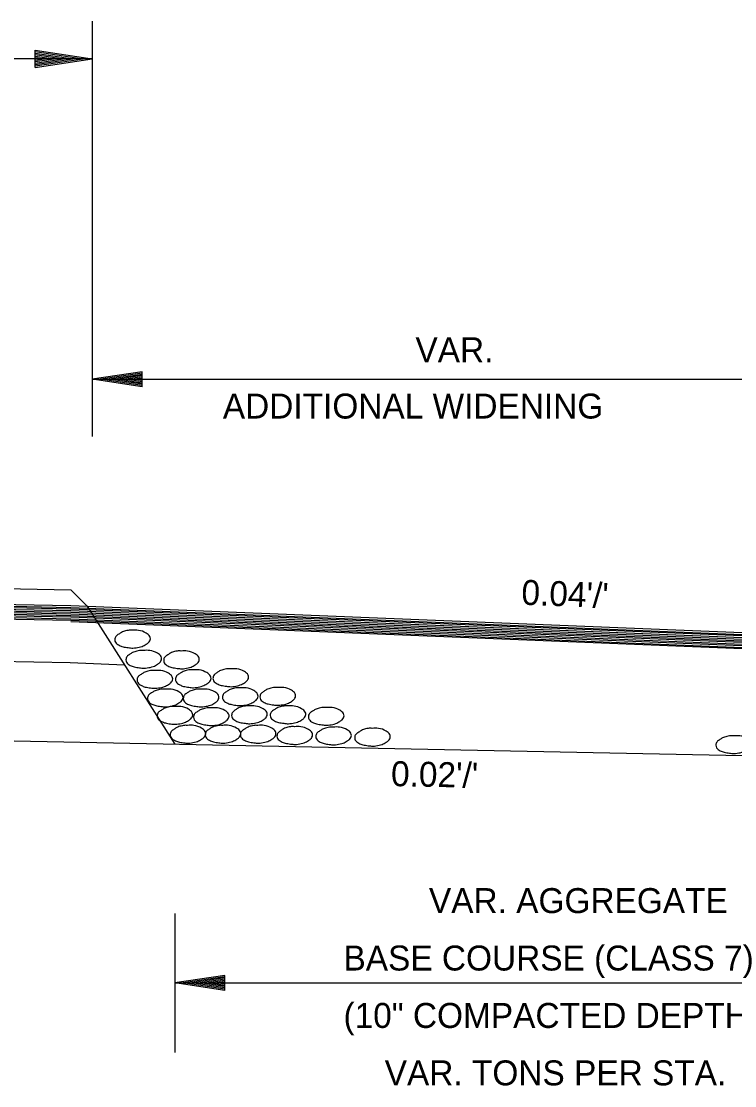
# Model space of a CAD drawing. Extents: x 1035 to 3550, y 35 to 1510.
# Drawn here: x 2318.4 to 2489.7, y 571 to 826.6 of the extents above; entities that cross this region are included whole.
import ezdxf

# ---------------------------------------------------------------- set-up
doc = ezdxf.new("R2010")
doc.units = 0
doc.layers.add('Default', color=7, linetype='Continuous')

msp = doc.modelspace()

# ---------------------------------------------------------------- linework, layer by layer
at = {"layer": 'Default'}
for p, q in [((2335.41, 826.63), (2335.41, 726.95)), ((2321.71, 819.67), (2335.41, 817.63)), ((2321.71, 815.57), (2321.71, 819.67)), ((2321.71, 819.34), (2333.14, 817.63)), ((2321.71, 818.98), (2330.77, 817.63)), ((2321.71, 818.65), (2328.48, 817.63)), ((2321.71, 818.28), (2326.17, 817.63)), ((2335.41, 817.63), (2055.5, 817.63)), ((2321.71, 817.95), (2323.89, 817.63)), ((2321.71, 815.57), (2335.41, 817.63)), ((2321.71, 816.94), (2326.17, 817.63)), ((2321.71, 816.25), (2330.77, 817.63)), ((2321.71, 815.91), (2333.14, 817.63)), ((2321.71, 816.61), (2328.48, 817.63)), ((2321.71, 817.3), (2323.89, 817.63)), ((2347.41, 742.45), (2335.41, 740.65)), ((2347.41, 742.15), (2337.41, 740.65)), ((2347.41, 741.84), (2339.48, 740.65)), ((2347.41, 741.54), (2341.48, 740.65)), ((2347.41, 738.85), (2347.41, 742.45)), ((2335.41, 740.65), (2512.84, 740.65)), ((2347.41, 738.85), (2335.41, 740.65)), ((2347.41, 739.15), (2337.41, 740.65)), ((2347.41, 739.46), (2339.48, 740.65)), ((2347.41, 739.76), (2341.48, 740.65)), ((2347.41, 741.24), (2343.51, 740.65)), ((2347.41, 740.07), (2343.51, 740.65)), ((2347.41, 740.93), (2345.51, 740.65)), ((2347.41, 740.37), (2345.51, 740.65)), ((2261.72, 687.66), (2330.33, 686.31)), ((2261.72, 687.24), (2330.33, 685.87)), ((2261.72, 686.92), (2330.33, 685.54)), ((2261.72, 686.51), (2330.33, 685.12)), ((2261.72, 686.11), (2330.33, 684.7)), ((2261.72, 685.73), (2330.33, 684.34)), ((2261.72, 685.34), (2330.33, 683.96)), ((2330.33, 686.31), (2557.51, 677.18)), ((2330.33, 685.87), (2557.79, 676.73)), ((2330.33, 685.54), (2557.97, 676.45)), ((2330.33, 685.12), (2558.27, 675.98)), ((2334.24, 686.17), (2355.28, 653.05)), ((2261.72, 684.95), (2330.33, 683.58)), ((2261.72, 684.52), (2330.33, 683.16)), ((2261.72, 684.14), (2330.33, 682.79)), ((2330.33, 684.7), (2558.52, 675.59)), ((2330.33, 684.34), (2558.81, 675.13)), ((2330.33, 683.96), (2559.01, 674.8)), ((2330.33, 683.58), (2559.3, 674.35)), ((2330.33, 683.16), (2559.55, 673.96)), ((2330.33, 682.79), (2559.84, 673.5)), ((2330.33, 682.46), (2560.01, 673.24)), ((2261.52, 673.98), (2330.13, 672.63)), ((2330.13, 672.63), (2343.16, 672.12)), ((2261.14, 654.92), (2647.44, 647.2)), ((2355.29, 612.37), (2355.29, 579.01)), ((2367.29, 597.49), (2355.29, 595.69)), ((2355.29, 595.69), (2557.51, 595.69)), ((2367.29, 593.89), (2355.29, 595.69)), ((2367.29, 597.19), (2357.29, 595.69)), ((2367.29, 594.19), (2357.29, 595.69)), ((2367.29, 596.88), (2359.36, 595.69)), ((2367.29, 594.5), (2359.36, 595.69)), ((2367.29, 596.58), (2361.36, 595.69)), ((2367.29, 594.8), (2361.36, 595.69)), ((2367.29, 596.28), (2363.39, 595.69)), ((2367.29, 595.11), (2363.39, 595.69)), ((2367.29, 595.97), (2365.39, 595.69)), ((2367.29, 595.41), (2365.39, 595.69)), ((2367.29, 593.89), (2367.29, 597.49))]:
    msp.add_line(p, q, dxfattribs=at)
msp.add_lwpolyline([(2261.72, 691.48), (2330.33, 690.11), (2334.24, 686.17)], dxfattribs=at)
for points in [[(2345.03, 680.37), (2346.56, 680.36), (2348.38, 679.72), (2349.27, 678.89), (2349.39, 678.35), (2348.93, 677.43), (2348.41, 677.04), (2347.41, 676.52), (2345.95, 676.18), (2345.19, 676.1), (2344.08, 676.21), (2342.82, 676.42), (2341.87, 676.79), (2340.99, 677.52), (2340.84, 678.1), (2341.1, 678.92), (2341.8, 679.45), (2342.44, 679.87), (2343.46, 680.22), (2344.09, 680.36), (2345.03, 680.37)], [(2347.72, 675.54), (2349.25, 675.53), (2351.07, 674.89), (2351.96, 674.06), (2352.08, 673.52), (2351.62, 672.6), (2351.1, 672.21), (2350.1, 671.69), (2348.64, 671.35), (2347.88, 671.27), (2346.77, 671.38), (2345.51, 671.59), (2344.56, 671.96), (2343.68, 672.69), (2343.53, 673.27), (2343.79, 674.09), (2344.49, 674.62), (2345.13, 675.04), (2346.15, 675.39), (2346.78, 675.53), (2347.72, 675.54)], [(2356.78, 675.4), (2358.31, 675.39), (2360.13, 674.75), (2361.02, 673.92), (2361.14, 673.38), (2360.68, 672.46), (2360.16, 672.07), (2359.16, 671.55), (2357.7, 671.21), (2356.94, 671.13), (2355.83, 671.24), (2354.57, 671.45), (2353.62, 671.82), (2352.74, 672.55), (2352.59, 673.13), (2352.85, 673.95), (2353.55, 674.48), (2354.19, 674.9), (2355.21, 675.25), (2355.84, 675.39), (2356.78, 675.4)], [(2350.39, 670.71), (2351.92, 670.7), (2353.74, 670.06), (2354.63, 669.23), (2354.75, 668.69), (2354.29, 667.77), (2353.77, 667.38), (2352.77, 666.86), (2351.31, 666.52), (2350.55, 666.44), (2349.44, 666.55), (2348.18, 666.76), (2347.23, 667.13), (2346.35, 667.86), (2346.2, 668.44), (2346.46, 669.26), (2347.16, 669.79), (2347.8, 670.21), (2348.82, 670.56), (2349.45, 670.7), (2350.39, 670.71)], [(2359.6, 670.86), (2361.13, 670.85), (2362.95, 670.21), (2363.84, 669.38), (2363.96, 668.84), (2363.5, 667.92), (2362.98, 667.53), (2361.98, 667.01), (2360.52, 666.67), (2359.76, 666.59), (2358.65, 666.7), (2357.39, 666.91), (2356.44, 667.28), (2355.56, 668.01), (2355.41, 668.59), (2355.67, 669.41), (2356.37, 669.94), (2357.01, 670.36), (2358.03, 670.71), (2358.66, 670.85), (2359.6, 670.86)], [(2368.62, 671.11), (2370.15, 671.1), (2371.97, 670.46), (2372.86, 669.63), (2372.98, 669.09), (2372.52, 668.17), (2372, 667.78), (2371, 667.26), (2369.54, 666.92), (2368.78, 666.84), (2367.67, 666.95), (2366.41, 667.16), (2365.46, 667.53), (2364.58, 668.26), (2364.43, 668.84), (2364.69, 669.66), (2365.39, 670.19), (2366.03, 670.61), (2367.05, 670.96), (2367.68, 671.1), (2368.62, 671.11)], [(2352.88, 666.25), (2354.41, 666.24), (2356.23, 665.6), (2357.12, 664.77), (2357.24, 664.23), (2356.78, 663.31), (2356.26, 662.92), (2355.26, 662.4), (2353.8, 662.06), (2353.04, 661.98), (2351.93, 662.09), (2350.67, 662.3), (2349.72, 662.67), (2348.84, 663.4), (2348.69, 663.98), (2348.95, 664.8), (2349.65, 665.33), (2350.29, 665.75), (2351.31, 666.1), (2351.94, 666.24), (2352.88, 666.25)], [(2361.49, 666.25), (2363.02, 666.24), (2364.84, 665.6), (2365.73, 664.77), (2365.85, 664.23), (2365.39, 663.31), (2364.87, 662.92), (2363.87, 662.4), (2362.41, 662.06), (2361.65, 661.98), (2360.54, 662.09), (2359.28, 662.3), (2358.33, 662.67), (2357.45, 663.4), (2357.3, 663.98), (2357.56, 664.8), (2358.26, 665.33), (2358.9, 665.75), (2359.92, 666.1), (2360.55, 666.24), (2361.49, 666.25)], [(2370.89, 666.55), (2372.42, 666.54), (2374.24, 665.9), (2375.13, 665.07), (2375.25, 664.53), (2374.79, 663.61), (2374.27, 663.22), (2373.27, 662.7), (2371.81, 662.36), (2371.05, 662.28), (2369.94, 662.39), (2368.68, 662.6), (2367.73, 662.97), (2366.85, 663.7), (2366.7, 664.28), (2366.96, 665.1), (2367.66, 665.63), (2368.3, 666.05), (2369.32, 666.4), (2369.95, 666.54), (2370.89, 666.55)], [(2379.91, 666.63), (2381.44, 666.62), (2383.26, 665.98), (2384.15, 665.15), (2384.27, 664.61), (2383.81, 663.69), (2383.29, 663.3), (2382.29, 662.78), (2380.83, 662.44), (2380.07, 662.36), (2378.96, 662.47), (2377.7, 662.68), (2376.75, 663.05), (2375.87, 663.78), (2375.72, 664.36), (2375.98, 665.18), (2376.68, 665.71), (2377.32, 666.13), (2378.34, 666.48), (2378.97, 666.62), (2379.91, 666.63)], [(2355.2, 662.07), (2356.73, 662.06), (2358.55, 661.42), (2359.44, 660.59), (2359.56, 660.05), (2359.1, 659.13), (2358.58, 658.74), (2357.58, 658.22), (2356.12, 657.88), (2355.36, 657.8), (2354.25, 657.91), (2352.99, 658.12), (2352.04, 658.49), (2351.16, 659.22), (2351.01, 659.8), (2351.27, 660.62), (2351.97, 661.15), (2352.61, 661.57), (2353.63, 661.92), (2354.26, 662.06), (2355.2, 662.07)], [(2373.1, 662.2), (2374.63, 662.19), (2376.45, 661.55), (2377.34, 660.72), (2377.46, 660.18), (2377, 659.26), (2376.48, 658.87), (2375.48, 658.35), (2374.02, 658.01), (2373.26, 657.93), (2372.15, 658.04), (2370.89, 658.25), (2369.94, 658.62), (2369.06, 659.35), (2368.91, 659.93), (2369.17, 660.75), (2369.87, 661.28), (2370.51, 661.7), (2371.53, 662.05), (2372.16, 662.19), (2373.1, 662.2)], [(2382.37, 662.2), (2383.9, 662.19), (2385.72, 661.55), (2386.61, 660.72), (2386.73, 660.18), (2386.27, 659.26), (2385.75, 658.87), (2384.75, 658.35), (2383.29, 658.01), (2382.53, 657.93), (2381.42, 658.04), (2380.16, 658.25), (2379.21, 658.62), (2378.33, 659.35), (2378.18, 659.93), (2378.44, 660.75), (2379.14, 661.28), (2379.78, 661.7), (2380.8, 662.05), (2381.43, 662.19), (2382.37, 662.2)], [(2363.95, 661.76), (2365.48, 661.75), (2367.3, 661.11), (2368.19, 660.28), (2368.31, 659.74), (2367.85, 658.82), (2367.33, 658.43), (2366.33, 657.91), (2364.87, 657.57), (2364.11, 657.49), (2363, 657.6), (2361.74, 657.81), (2360.79, 658.18), (2359.91, 658.91), (2359.76, 659.49), (2360.02, 660.31), (2360.72, 660.84), (2361.36, 661.26), (2362.38, 661.61), (2363.01, 661.75), (2363.95, 661.76)], [(2391.54, 661.84), (2393.07, 661.83), (2394.89, 661.19), (2395.78, 660.36), (2395.9, 659.82), (2395.44, 658.9), (2394.92, 658.51), (2393.92, 657.99), (2392.46, 657.65), (2391.7, 657.57), (2390.59, 657.68), (2389.33, 657.89), (2388.38, 658.26), (2387.5, 658.99), (2387.35, 659.57), (2387.61, 660.39), (2388.31, 660.92), (2388.95, 661.34), (2389.97, 661.69), (2390.6, 661.83), (2391.54, 661.84)], [(2358.33, 657.54), (2359.86, 657.53), (2361.68, 656.89), (2362.57, 656.06), (2362.69, 655.52), (2362.23, 654.6), (2361.71, 654.21), (2360.71, 653.69), (2359.25, 653.35), (2358.49, 653.27), (2357.38, 653.38), (2356.12, 653.59), (2355.17, 653.96), (2354.29, 654.69), (2354.14, 655.27), (2354.4, 656.09), (2355.1, 656.62), (2355.74, 657.04), (2356.76, 657.39), (2357.39, 657.53), (2358.33, 657.54)], [(2366.76, 657.54), (2368.29, 657.53), (2370.11, 656.89), (2371, 656.06), (2371.12, 655.52), (2370.66, 654.6), (2370.14, 654.21), (2369.14, 653.69), (2367.68, 653.35), (2366.92, 653.27), (2365.81, 653.38), (2364.55, 653.59), (2363.6, 653.96), (2362.72, 654.69), (2362.57, 655.27), (2362.83, 656.09), (2363.53, 656.62), (2364.17, 657.04), (2365.19, 657.39), (2365.82, 657.53), (2366.76, 657.54)], [(2375.2, 657.54), (2376.73, 657.53), (2378.55, 656.89), (2379.44, 656.06), (2379.56, 655.52), (2379.1, 654.6), (2378.58, 654.21), (2377.58, 653.69), (2376.12, 653.35), (2375.36, 653.27), (2374.25, 653.38), (2372.99, 653.59), (2372.04, 653.96), (2371.16, 654.69), (2371.01, 655.27), (2371.27, 656.09), (2371.97, 656.62), (2372.61, 657.04), (2373.63, 657.39), (2374.26, 657.53), (2375.2, 657.54)], [(2383.99, 657.23), (2385.52, 657.22), (2387.34, 656.58), (2388.23, 655.75), (2388.35, 655.21), (2387.89, 654.29), (2387.37, 653.9), (2386.37, 653.38), (2384.91, 653.04), (2384.15, 652.96), (2383.04, 653.07), (2381.78, 653.28), (2380.83, 653.65), (2379.95, 654.38), (2379.8, 654.96), (2380.06, 655.78), (2380.76, 656.31), (2381.4, 656.73), (2382.42, 657.08), (2383.05, 657.22), (2383.99, 657.23)], [(2393.32, 657.13), (2394.85, 657.12), (2396.67, 656.48), (2397.56, 655.65), (2397.68, 655.11), (2397.22, 654.19), (2396.7, 653.8), (2395.7, 653.28), (2394.24, 652.94), (2393.48, 652.86), (2392.37, 652.97), (2391.11, 653.18), (2390.16, 653.55), (2389.28, 654.28), (2389.13, 654.86), (2389.39, 655.68), (2390.09, 656.21), (2390.73, 656.63), (2391.75, 656.98), (2392.38, 657.12), (2393.32, 657.13)], [(2402.66, 656.83), (2404.19, 656.82), (2406.01, 656.18), (2406.9, 655.35), (2407.02, 654.81), (2406.56, 653.89), (2406.04, 653.5), (2405.04, 652.98), (2403.58, 652.64), (2402.82, 652.56), (2401.71, 652.67), (2400.45, 652.88), (2399.5, 653.25), (2398.62, 653.98), (2398.47, 654.56), (2398.73, 655.38), (2399.43, 655.91), (2400.07, 656.33), (2401.09, 656.68), (2401.72, 656.82), (2402.66, 656.83)], [(2489.42, 655.04), (2490.95, 655.03), (2492.77, 654.39), (2493.66, 653.56), (2493.78, 653.02), (2493.32, 652.1), (2492.8, 651.71), (2491.8, 651.19), (2490.34, 650.85), (2489.58, 650.77), (2488.47, 650.88), (2487.21, 651.09), (2486.26, 651.46), (2485.38, 652.19), (2485.23, 652.77), (2485.49, 653.59), (2486.19, 654.12), (2486.83, 654.54), (2487.85, 654.89), (2488.48, 655.03), (2489.42, 655.04)]]:
    msp.add_spline(points, degree=3, dxfattribs=at)

# ---------------------------------------------------------------- texts
for s, p in [('VAR.', (2413.06, 744.73)), ('ADDITIONAL WIDENING', (2366.8, 731.23)), ('VAR. AGGREGATE', (2416.3, 612.46)), ('BASE COURSE (CLASS 7)', (2395.78, 598.67)), ('(10" COMPACTED DEPTH)', (2395.78, 584.88)), ('VAR. TONS PER STA.', (2405.68, 571.09))]:
    msp.add_text(s, height=6, dxfattribs=at).set_placement(p)
for s, rotation, p in [("0.04'/'", 357.7077, (2438.42, 686.54)), ("0.02'/'", 358.8543, (2407.15, 642.97))]:
    msp.add_text(s, height=6, rotation=rotation, dxfattribs=at).set_placement(p)

doc.saveas('drawing.dxf')
